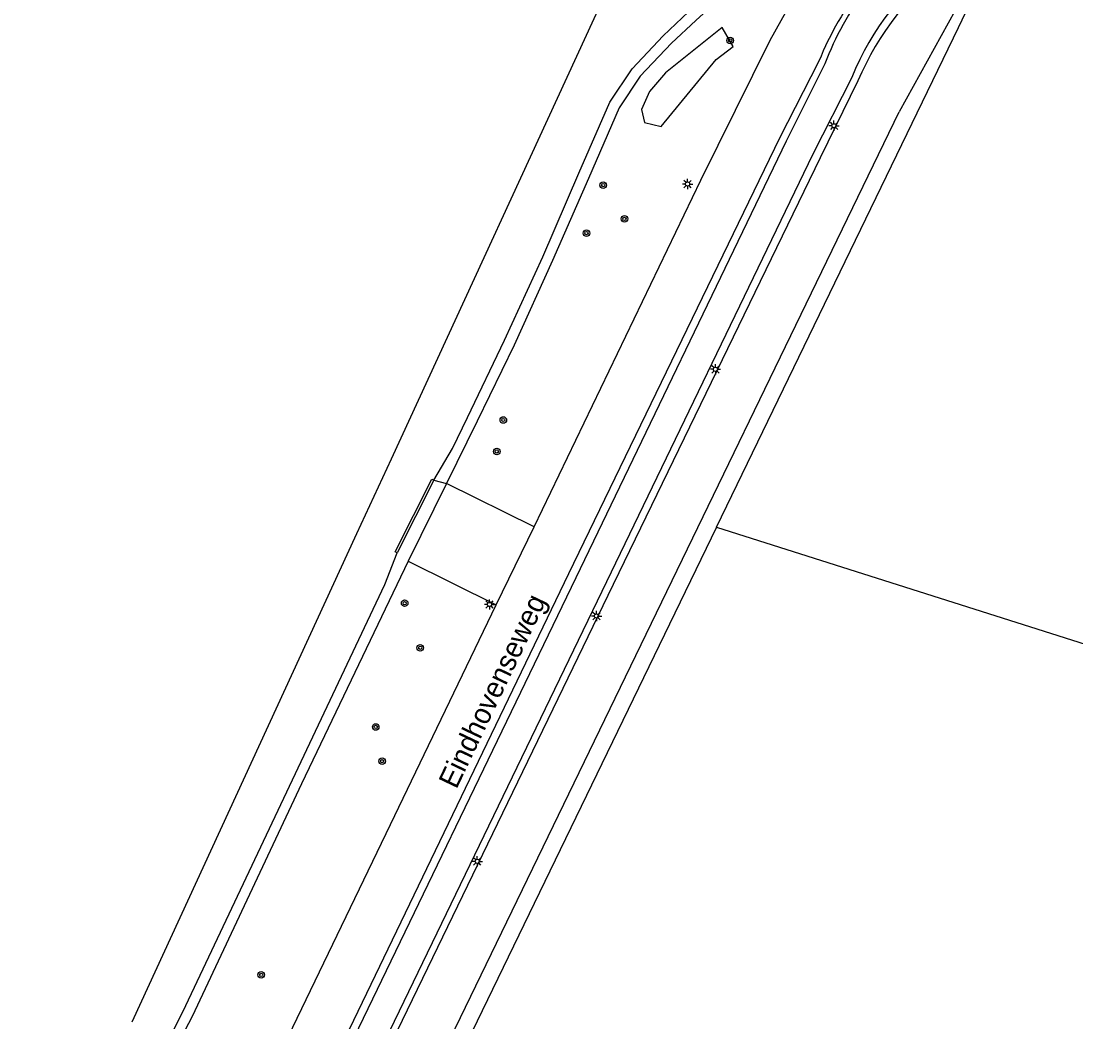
# Model space of a CAD drawing. Extents: x 135990 to 139000, y 393500 to 396000.
# Drawn here: x 137032.7 to 137160.7, y 395078.3 to 395199.8 of the extents above; entities that cross this region are included whole.
import ezdxf

# ---------------------------------------------------------------- set-up
doc = ezdxf.new("R2010")
doc.units = 0
for name, color, linetype in [('gg-afsc-faunaraster', 7, 'Continuous'), ('gg-afsc-muur', 7, 'Continuous'), ('gg-anno-openbare ruimte label', 7, 'Continuous'), ('gg-knt-verharding', 7, 'Continuous'), ('gg-kntw-bovenkant insteek waterloop', 7, 'Continuous'), ('gt-grn-groengrens', 7, 'Continuous'), ('gt-grn-vlakafsluiter', 7, 'Continuous'), ('gt-grn-weggrens', 7, 'Continuous'), ('gt-symb-boom', 7, 'Continuous'), ('gt-symb-lichtmast', 7, 'Continuous')]:
    doc.layers.add(name, color=color, linetype=linetype)

# ---------------------------------------------------------------- blocks, each defined once
blk = doc.blocks.new('gt0-BOOM')
at = {"layer": 'gt-symb-boom'}
for radius in [0.4, 0.2]:
    blk.add_circle((0, 0), radius, dxfattribs=at)
blk = doc.blocks.new('gt0-LMAST')
at = {"layer": 'gt-symb-lichtmast'}
for p, q in [((-0.18, 0.17), (-0.45, 0.44)), ((-0.01, 0.25), (-0.01, 0.62)), ((0.17, 0.17), (0.44, 0.44)), ((-0.26, 0), (-0.63, 0)), ((-0.18, -0.18), (-0.45, -0.45)), ((-0.01, -0.25), (-0.01, -0.63)), ((0.44, -0.45), (0.17, -0.18)), ((0.24, 0), (0.62, 0))]:
    blk.add_line(p, q, dxfattribs=at)
blk.add_circle((-0.01, 0), 0.25, dxfattribs=at)

msp = doc.modelspace()

# ---------------------------------------------------------------- linework, layer by layer
at = {"layer": 'gg-afsc-faunaraster'}
for p, q in [((137077.671, 395146.654), (137118.306, 395234.953)), ((137046.23, 395078.295), (137073.484, 395137.585))]:
    msp.add_line(p, q, dxfattribs=at)
at = {"layer": 'gg-afsc-muur'}
for q in [(137146.49, 395199.011), (137146.49, 395199.011), (137187.73, 395115.93), (137187.73, 395115.93)]:
    msp.add_line((137117.126, 395138.354), q, dxfattribs=at)
msp.add_lwpolyline([(137117.126, 395138.354), (137065.97, 395032.681), (137068.11, 395031.392), (137070.74, 395029.05), (137074.6, 395023.85), (137077.45, 395017.38), (137078.402, 395008.103)], dxfattribs=at)
at = {"layer": 'gg-knt-verharding'}
for p, q in [((137082.836, 395144.079), (137078.374, 395135.229)), ((137084.373, 395143.667), (137079.694, 395134.245)), ((137094.994, 395138.386), (137084.373, 395143.667)), ((137090.395, 395128.927), (137094.994, 395138.386)), ((137079.694, 395134.245), (137090.395, 395128.927))]:
    msp.add_line(p, q, dxfattribs=at)
for points in [[(137082.836, 395144.079), (137085.086, 395147.913), (137086.917, 395151.667), (137091.417, 395161.06), (137096.036, 395171.172), (137100.409, 395181.355), (137104.168, 395189.954), (137106.877, 395194.019), (137110.666, 395197.999), (137113.74, 395200.904), (137116.769, 395203.689), (137118.266, 395205.926), (137118.833, 395207.796), (137118.812, 395210.375), (137118.318, 395211.966), (137117.136, 395214.328), (137116.13, 395217.073), (137115.904, 395220.443), (137116.444, 395223.298), (137118.244, 395226.691), (137120.705, 395229.218), (137124.717, 395231.576), (137126.962, 395232.816)], [(137129.627, 395232.818), (137125.424, 395230.429), (137121.494, 395227.972), (137119.241, 395225.817), (137117.77, 395223.019), (137117.295, 395220.41), (137117.515, 395217.3), (137118.414, 395214.859), (137119.549, 395212.629), (137120.241, 395210.558), (137120.225, 395207.618), (137119.498, 395205.212), (137117.87, 395202.861), (137114.604, 395199.858), (137111.666, 395197.108), (137107.851, 395193.112), (137105.305, 395189.263), (137101.605, 395180.703), (137097.225, 395170.726), (137092.557, 395160.466), (137088.097, 395151.207), (137084.373, 395143.667)], [(137094.994, 395138.386), (137115.233, 395180.488), (137123.629, 395197.49), (137128.763, 395206.722)], [(137129.558, 395194.937), (137124.78, 395185.575), (137099.168, 395132.697), (137068.909, 395069.816), (137059.839, 395050.838)], [(137130.285, 395194.594), (137125.578, 395185.214), (137100.042, 395132.212), (137069.749, 395069.391), (137065.304, 395059.73)], [(137133.544, 395192.94), (137128.828, 395183.626), (137103.204, 395130.528), (137072.864, 395067.708), (137068.555, 395058.283), (137065.41, 395049.873), (137061.265, 395040.771), (137058.568, 395035.928), (137054.623, 395028.909)], [(137078.374, 395135.229), (137078.149, 395135.352), (137082.581, 395144.188), (137082.836, 395144.079)], [(137032.731, 395057), (137039.062, 395061.344), (137044.171, 395066.223), (137047.481, 395070.5), (137049.221, 395073.331), (137052.352, 395079.506), (137076.861, 395131.4), (137078.374, 395135.229)], [(137079.694, 395134.245), (137066.779, 395107.202), (137053.48, 395078.944), (137049.857, 395071.975), (137048.517, 395069.869), (137047.503, 395067.294), (137046.687, 395064.953), (137043.935, 395056.892), (137044.275, 395056.661)], [(137054.151, 395053.526), (137064.098, 395074.312), (137077.577, 395102.252), (137090.395, 395128.927)]]:
    msp.add_lwpolyline(points, dxfattribs=at)
for centre, radius, start, end in [((137167.328, 395179.452), 40.821, 127.69581, 157.70676), ((137162.934, 395182.435), 34.84, 125.08004, 159.57378), ((137165.093, 395180.194), 34.027, 126.03715, 158.00048)]:
    msp.add_arc(centre, radius, start, end, dxfattribs=at)
at = {"layer": 'gg-kntw-bovenkant insteek waterloop'}
for points in [[(137147.889, 395201.901), (137147.755, 395202), (137146.927, 395202.652), (137139.294, 395188.782)], [(137134.294, 395192.539), (137129.706, 395183.177), (137103.944, 395130.079), (137073.529, 395067.163), (137069.395, 395057.903), (137066.212, 395049.512), (137062.326, 395040.422), (137059.746, 395035.039)], [(137077.041, 395008.588), (137075.18, 395018.29), (137071.65, 395024.3), (137064.06, 395032.41), (137064.15, 395033.562), (137139.294, 395188.782)]]:
    msp.add_lwpolyline(points, dxfattribs=at)
msp.add_arc((137165.989, 395179.252), 34.367, 126.18655, 157.256, dxfattribs=at)
at = {"layer": 'gt-grn-groengrens'}
msp.add_line((137146.49, 395199.011), (137147.889, 395201.901), dxfattribs=at)
msp.add_lwpolyline([(137117.823, 395199.026), (137110.938, 395193.498), (137108.995, 395191.246), (137108.044, 395189.06), (137108.372, 395187.502), (137110.417, 395186.988), (137117.087, 395195.128), (137119.159, 395196.727), (137117.823, 395199.026)], dxfattribs=at)
at = {"layer": 'gt-grn-vlakafsluiter'}
msp.add_line((137073.484, 395137.585), (137077.671, 395146.654), dxfattribs=at)
at = {"layer": 'gt-grn-weggrens'}
msp.add_line((137082.836, 395144.079), (137084.373, 395143.667), dxfattribs=at)

# ---------------------------------------------------------------- block references
at = {"layer": 'gt-symb-boom'}
for p in [(137118.79, 395197.443), (137103.379, 395179.89), (137105.955, 395175.788), (137101.345, 395174.06), (137091.256, 395151.367), (137090.452, 395147.55), (137079.282, 395129.126), (137081.178, 395123.717), (137075.767, 395114.102), (137076.547, 395109.95), (137061.872, 395084)]:
    msp.add_blockref('gt0-BOOM', p, dxfattribs=at)
at = {"layer": 'gt-symb-lichtmast'}
for p in [(137131.392, 395187.092), (137113.623, 395180.016), (137117.009, 395157.523), (137089.591, 395128.977), (137102.571, 395127.568), (137088.099, 395097.783)]:
    msp.add_blockref('gt0-LMAST', p, dxfattribs=at)

# ---------------------------------------------------------------- texts
at = {"layer": 'gg-anno-openbare ruimte label'}
msp.add_text('Eindhovenseweg', height=2.5, rotation=64.5, dxfattribs=at).set_placement((137085.559, 395106.46))

doc.saveas('drawing.dxf')
